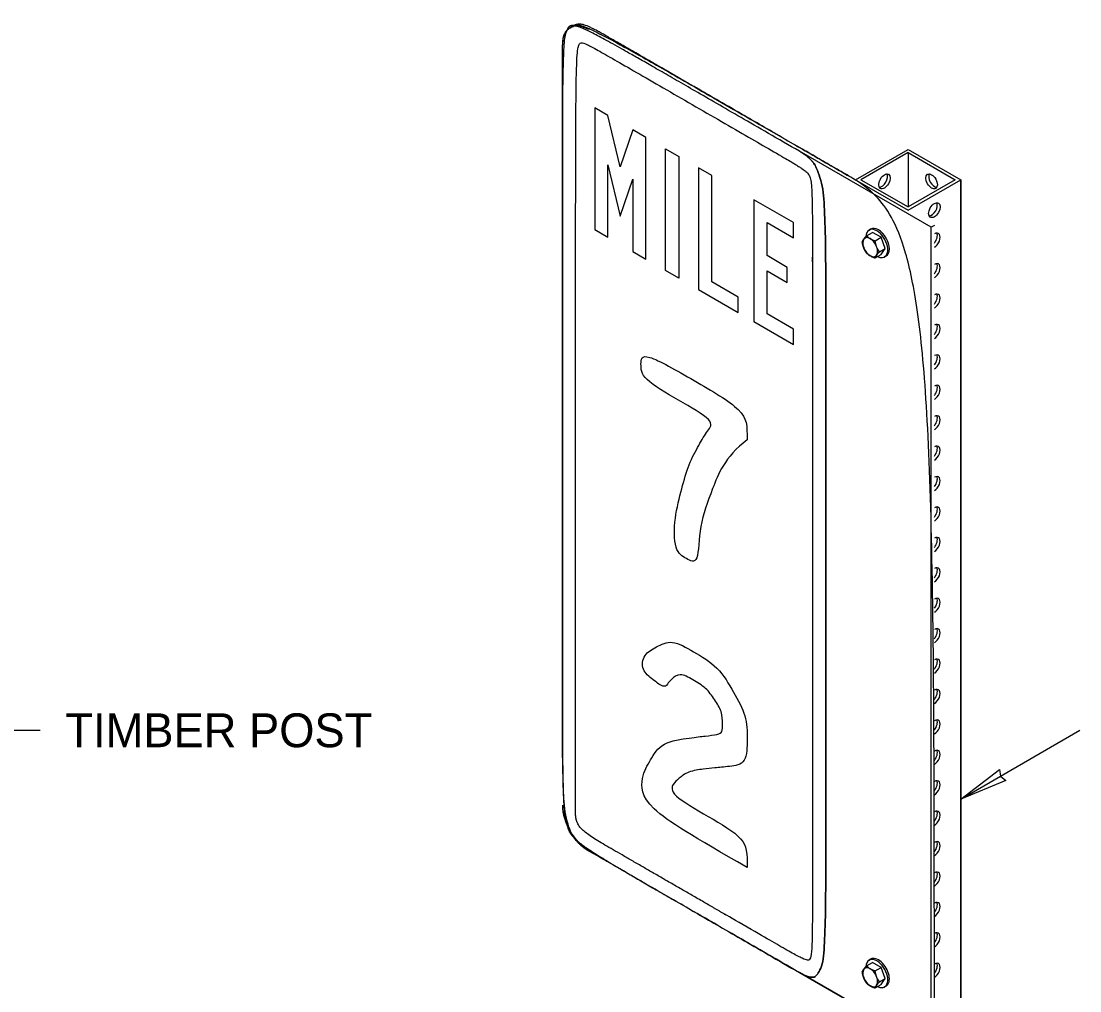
# Model space of a CAD drawing. Extents: x 99862 to 103151, y 100000 to 102076.
# Drawn here: x 102287 to 102788, y 101046 to 101505 of the extents above; entities that cross this region are included whole.
import ezdxf

# ---------------------------------------------------------------- set-up
doc = ezdxf.new("R2010")
doc.units = 0
for name, color, linetype in [('Level 15', 7, 'Continuous'), ('Level 2', 7, 'Continuous'), ('Level 20', 7, 'Continuous'), ('Level 9', 7, 'Continuous')]:
    doc.layers.add(name, color=color, linetype=linetype)

msp = doc.modelspace()

# ---------------------------------------------------------------- linework, layer by layer
at = {"layer": 'Level 15'}
for p, q in [((102280.36, 101169.56), (102296.36, 101169.56)), ((102731.44, 101137.06), (102787.74, 101169.56))]:
    msp.add_line(p, q, dxfattribs=at)
msp.add_lwpolyline([(102731.45, 101137.06), (102749.72, 101151.06), (102750.3, 101147.95), (102752.71, 101145.89)], close=True, dxfattribs=at)
at = {"layer": 'Level 2'}
for p, q in [((102548.42, 101502.35), (102546.86, 101501.45)), ((102681.67, 101429.63), (102706.56, 101444)), ((102706.56, 101442.49), (102684.28, 101429.63)), ((102706.56, 101444), (102731.45, 101429.63)), ((102706.56, 101442.49), (102706.56, 101416.77)), ((102706.56, 101442.49), (102728.83, 101429.63)), ((102715.77, 101432.21), (102715.77, 101432.21)), ((102681.67, 101429.63), (102706.56, 101415.26)), ((102684.28, 101429.63), (102706.56, 101416.77)), ((102728.83, 101429.63), (102706.56, 101416.77)), ((102706.56, 101415.26), (102731.45, 101429.63)), ((102731.45, 100984.15), (102731.45, 101429.63)), ((102719.62, 101425.54), (102719.62, 101425.54)), ((102719, 101408.07), (102717.45, 101407.17)), ((102720.93, 101404.22), (102720.93, 101404.22)), ((102720.93, 101389.85), (102720.93, 101389.85)), ((102720.93, 101375.48), (102720.93, 101375.48)), ((102720.93, 101274.89), (102720.93, 101274.89)), ((102720.93, 101260.52), (102720.93, 101260.52)), ((102720.93, 101116.82), (102720.93, 101116.82)), ((102720.93, 101059.33), (102720.93, 101059.33))]:
    msp.add_line(p, q, dxfattribs=at)
for points in [[(102546.86, 101501.45), (102548.42, 101502.35)], [(102546.86, 101501.45), (102546.86, 101501.45), (102546.86, 101501.45)], [(102655.22, 101055.1), (102717.45, 101019.18), (102717.45, 101407.17), (102655.22, 101443.1)], [(102706.56, 101025.46), (102717.45, 101019.18), (102717.45, 101407.17), (102655.22, 101443.1)], [(102681.67, 101429.63), (102706.56, 101444), (102731.45, 101429.63), (102731.45, 101029.06)], [(102688.11, 101405.89), (102688.89, 101406.34)], [(102685.6, 101401.49), (102685.67, 101401.59)], [(102685.68, 101397.37), (102685.59, 101397.62)], [(102688.75, 101393.68), (102688.58, 101393.78)], [(102692.1, 101393.38), (102692.1, 101393.38), (102692.1, 101393.38), (102692.04, 101393.34), (102691, 101392.74)], [(102696.22, 101393.64), (102696.1, 101393.74)], [(102688.11, 101061), (102688.89, 101061.45)], [(102685.6, 101056.6), (102685.67, 101056.7)], [(102681.67, 101027.26), (102681.67, 101039.83), (102655.22, 101055.1)], [(102655.22, 101055.1), (102681.67, 101039.83), (102706.56, 101025.46)], [(102685.68, 101052.49), (102685.59, 101052.73)], [(102688.75, 101048.79), (102688.58, 101048.89)], [(102692.1, 101048.49), (102692.1, 101048.49), (102692.1, 101048.49), (102692.04, 101048.45), (102691, 101047.85)], [(102696.22, 101048.75), (102696.1, 101048.85)]]:
    msp.add_lwpolyline(points, dxfattribs=at)
for points in [[(102564.74, 101459.95), (102558.52, 101463.54), (102558.52, 101406.06), (102564.74, 101402.47), (102564.74, 101436.62), (102570.59, 101412.37), (102576.44, 101429.86), (102576.44, 101395.71), (102582.67, 101392.12), (102582.67, 101449.6), (102576.44, 101453.2), (102570.59, 101435.71)], [(102592, 101444.21), (102598.22, 101440.62), (102598.22, 101383.14), (102592, 101386.73)], [(102626.22, 101374.16), (102613.78, 101381.34), (102613.78, 101431.64), (102607.56, 101435.23), (102607.56, 101377.75), (102626.22, 101366.97)], [(102649.49, 101388.26), (102639.91, 101393.79), (102639.91, 101409.37), (102652.36, 101402.18), (102652.36, 101409.37), (102633.69, 101420.14), (102633.69, 101362.66), (102652.36, 101351.88), (102652.36, 101359.07), (102639.91, 101366.26), (102639.91, 101386.61), (102649.49, 101381.08)]]:
    msp.add_lwpolyline(points, close=True, dxfattribs=at)
for centre, major_axis, start_param, end_param in [((102555.66, 101486.21), (-8.8, 15.24), 5.497787, 7.068583), ((102555.66, 101486.21), (-8.8, 15.24), 6.113032, 6.283048), ((102555.66, 101486.21), (-8.8, 15.24), 6.283048, 6.283185), ((102555.66, 101486.21), (-8.8, 15.24), 0.517036, 0.785398), ((102694.11, 101429.63), (-1.92, -3.33), 0.346291, 2.795302), ((102719, 101429.63), (1.92, -3.33), 3.487884, 5.936894), ((102717.69, 101416.01), (-1.92, -3.33), 0.346291, 2.795302), ((102692.56, 101399.99), (3.67, -6.35), 6.283184, 9.424776), ((102691.78, 101399.54), (3.67, -6.35), 3.141591, 3.891684), ((102719, 101400.89), (-1.92, -3.33), 0.785398, 3.926991), ((102717.69, 101401.64), (-1.92, -3.33), 1.286053, 2.795302), ((102691.78, 101399.54), (3.67, -6.35), 5.560453, 6.484335), ((102719, 101386.52), (-1.92, -3.33), 0.785398, 3.926991), ((102717.69, 101387.27), (-1.92, -3.33), 1.286053, 2.795302), ((102719, 101372.15), (-1.92, -3.33), 0.785398, 3.926991), ((102717.69, 101372.9), (-1.92, -3.33), 1.286053, 2.795302), ((102719, 101357.78), (-1.92, -3.33), 0.785398, 3.926991), ((102717.69, 101358.53), (-1.92, -3.33), 1.286053, 2.795302), ((102719, 101343.41), (-1.92, -3.33), 0.785398, 3.926991), ((102717.69, 101344.16), (-1.92, -3.33), 1.286053, 2.795302), ((102719, 101329.04), (-1.92, -3.33), 0.785398, 3.926991), ((102717.69, 101329.79), (-1.92, -3.33), 1.286053, 2.795302), ((102719, 101314.67), (-1.92, -3.33), 0.785398, 3.926991), ((102717.69, 101315.42), (-1.92, -3.33), 1.286053, 2.795302), ((102719, 101300.3), (-1.92, -3.33), 0.785398, 3.926991), ((102717.69, 101301.05), (-1.92, -3.33), 1.286053, 2.795302), ((102719, 101285.93), (-1.92, -3.33), 0.785398, 3.926991), ((102717.69, 101286.68), (-1.92, -3.33), 1.286053, 2.795302), ((102719, 101271.55), (-1.92, -3.33), 0.785398, 3.926991), ((102717.69, 101272.31), (-1.92, -3.33), 1.286053, 2.795302), ((102719, 101257.18), (-1.92, -3.33), 0.785398, 3.926991), ((102717.69, 101257.94), (-1.92, -3.33), 1.286053, 2.795302), ((102719, 101242.81), (-1.92, -3.33), 0.785398, 3.926991), ((102717.69, 101243.57), (-1.92, -3.33), 1.286053, 2.795302), ((102719, 101228.44), (-1.92, -3.33), 0.785398, 3.926991), ((102717.69, 101229.2), (-1.92, -3.33), 1.286053, 2.795302), ((102719, 101214.07), (-1.92, -3.33), 0.785398, 3.926991), ((102717.69, 101214.83), (-1.92, -3.33), 1.286053, 2.795302), ((102719, 101199.7), (-1.92, -3.33), 0.785398, 3.926991), ((102717.69, 101200.46), (-1.92, -3.33), 1.286053, 2.795302), ((102719, 101185.33), (-1.92, -3.33), 0.785398, 3.926991), ((102717.69, 101186.09), (-1.92, -3.33), 1.286053, 2.795302), ((102719, 101170.96), (-1.92, -3.33), 0.785398, 3.926991), ((102717.69, 101171.72), (-1.92, -3.33), 1.286053, 2.795302), ((102719, 101156.59), (-1.92, -3.33), 0.785398, 3.926991), ((102717.69, 101157.35), (-1.92, -3.33), 1.286053, 2.795302), ((102719, 101142.22), (-1.92, -3.33), 0.785398, 3.926991), ((102717.69, 101142.98), (-1.92, -3.33), 1.286053, 2.795302), ((102555.66, 101126.95), (8.8, -15.24), 3.926991, 5.497787), ((102719, 101127.85), (-1.92, -3.33), 0.785398, 3.926991), ((102717.69, 101128.61), (-1.92, -3.33), 1.286053, 2.795302), ((102719, 101113.48), (-1.92, -3.33), 0.785398, 3.926991), ((102717.69, 101114.24), (-1.92, -3.33), 1.286053, 2.795302), ((102719, 101099.11), (-1.92, -3.33), 0.785398, 3.926991), ((102717.69, 101099.87), (-1.92, -3.33), 1.286053, 2.795302), ((102719, 101084.74), (-1.92, -3.33), 0.785398, 3.926991), ((102717.69, 101085.49), (-1.92, -3.33), 1.286053, 2.795302), ((102719, 101070.37), (-1.92, -3.33), 0.785398, 3.926991), ((102717.69, 101071.12), (-1.92, -3.33), 1.286053, 2.795302), ((102692.56, 101055.1), (3.67, -6.35), 6.283185, 9.424778), ((102691.78, 101054.65), (3.67, -6.35), 3.141593, 3.891684), ((102691.78, 101054.65), (3.67, -6.35), 3.141466, 3.141593), ((102719, 101056), (-1.92, -3.33), 0.785398, 3.926991), ((102717.69, 101056.75), (-1.92, -3.33), 1.286053, 2.795302), ((102691.78, 101054.65), (3.67, -6.35), 5.560453, 6.484337)]:
    msp.add_ellipse(centre, major_axis=major_axis, ratio=0.57735, start_param=start_param, end_param=end_param, dxfattribs=at)
for centre, major_axis in [((102695.42, 101428.87), (-1.92, -3.33)), ((102717.69, 101428.87), (1.92, -3.33)), ((102719, 101415.26), (-1.92, -3.33))]:
    msp.add_ellipse(centre, major_axis=major_axis, ratio=0.57735, dxfattribs=at)
for points, degree in [([(102655.22, 101443.1), (102605.44, 101471.84), (102555.66, 101500.58), (102543.21, 101507.77), (102543.21, 101493.4), (102543.21, 101313.77), (102543.21, 101134.14), (102543.21, 101119.77), (102555.66, 101112.58), (102605.44, 101083.84), (102655.22, 101055.1)], 4), ([(102543.66, 101496.95), (102544.84, 101501.23), (102548.48, 101502.09)], 2), ([(102719, 101020.07), (102719, 101214.07), (102719, 101408.07), (102687.89, 101426.04), (102656.78, 101444), (102607, 101472.74), (102557.22, 101501.48), (102552.06, 101504.46), (102548.42, 101502.35)], 4), ([(102548.42, 101502.35), (102552.06, 101504.46), (102557.22, 101501.48), (102607, 101472.74), (102681.67, 101429.63)], 4), ([(102554.07, 101113.62), (102543.21, 101121.5), (102543.21, 101134.14), (102543.21, 101313.77), (102543.21, 101493.4), (102543.21, 101493.4), (102543.21, 101493.4)], 4), ([(102549.44, 101130.55), (102549.44, 101123.36), (102555.66, 101119.77), (102605.44, 101091.03), (102655.22, 101062.29), (102661.44, 101058.69), (102661.44, 101065.88), (102661.44, 101245.51), (102661.44, 101425.14), (102661.44, 101432.32), (102655.22, 101435.92), (102605.44, 101464.66), (102555.66, 101493.4), (102549.44, 101496.99), (102549.44, 101489.8), (102549.44, 101310.18), (102549.44, 101130.55)], 4), ([(102655.22, 101055.1), (102667.67, 101047.92), (102667.67, 101062.29), (102667.67, 101241.92), (102667.67, 101421.55), (102667.67, 101435.92), (102655.22, 101443.1)], 4), ([(102655.22, 101443.1), (102667.67, 101435.92), (102667.67, 101421.55), (102667.67, 101241.92), (102667.67, 101062.29), (102667.67, 101047.92), (102655.22, 101055.1)], 4), ([(102684.94, 101400.28), (102685.07, 101400.63), (102685.28, 101401.02), (102685.6, 101401.49)], 2), ([(102685.67, 101401.59), (102685.93, 101401.95), (102686.24, 101402.34), (102686.6, 101402.74)], 2), ([(102685.59, 101397.62), (102685.27, 101398.47), (102685.07, 101399.36), (102684.94, 101400.28)], 2), ([(102686.96, 101395.07), (102686.46, 101395.78), (102686.02, 101396.54), (102685.68, 101397.37)], 2), ([(102688.58, 101393.78), (102687.94, 101394.16), (102687.41, 101394.61), (102686.96, 101395.07)], 2), ([(102691, 101392.74), (102690.19, 101393), (102689.42, 101393.3), (102688.75, 101393.68)], 2), ([(102630.52, 101306.83), (102630.52, 101313.57), (102630.52, 101320.3), (102605.44, 101334.78), (102580.36, 101349.27), (102580.36, 101342.53), (102580.36, 101335.79), (102598.09, 101325.56), (102615.82, 101315.32), (102611.74, 101311.34), (102607.89, 101304.54), (102602.76, 101295.38), (102599.72, 101284.06), (102595.99, 101270.05), (102595.99, 101254.02), (102601.82, 101250.65), (102607.66, 101247.28), (102607.66, 101266.41), (102613.72, 101282.44), (102619.79, 101298.48), (102630.52, 101306.83)], 3), ([(102630.52, 101104.75), (102630.52, 101111.48), (102630.52, 101118.22), (102612.15, 101128.83), (102593.77, 101139.44), (102595.41, 101144.42), (102598.09, 101146.65), (102602.41, 101150.22), (102610.34, 101151.29), (102614.77, 101151.83), (102622.01, 101152.37), (102630.52, 101153.65), (102630.52, 101165.64), (102630.52, 101176.28), (102624.22, 101187.33), (102617.11, 101199.79), (102604.86, 101206.87), (102594.82, 101212.66), (102587.59, 101208.89), (102581.41, 101205.59), (102580.36, 101197.84), (102586.07, 101193.46), (102591.79, 101189.08), (102593.31, 101192.25), (102594.59, 101193.39), (102598.56, 101197.03), (102604.86, 101193.39), (102611.27, 101189.69), (102615.07, 101184.06), (102618.86, 101178.44), (102618.86, 101172.38), (102618.86, 101168.6), (102616.99, 101167.53), (102610.69, 101166.85), (102604.51, 101166.11), (102589.81, 101164.09), (102584.79, 101155.4), (102580.36, 101147.86), (102580.36, 101133.71), (102605.44, 101119.23), (102630.52, 101104.75)], 3), ([(102546.86, 101121.87), (102550.5, 101115.56), (102555.66, 101112.58)], 2), ([(102555.66, 101112.58), (102554.86, 101113.04), (102554.07, 101113.62)], 2), ([(102655.22, 101055.1), (102605.44, 101083.84), (102555.66, 101112.58), (102555.66, 101112.58), (102555.66, 101112.58)], 4), ([(102684.94, 101055.39), (102685.07, 101055.74), (102685.28, 101056.13), (102685.6, 101056.6)], 2), ([(102685.67, 101056.7), (102685.93, 101057.06), (102686.24, 101057.45), (102686.6, 101057.86)], 2), ([(102685.59, 101052.73), (102685.27, 101053.58), (102685.07, 101054.48), (102684.94, 101055.39)], 2), ([(102686.96, 101050.19), (102686.46, 101050.89), (102686.02, 101051.65), (102685.68, 101052.49)], 2), ([(102688.58, 101048.89), (102687.94, 101049.27), (102687.41, 101049.72), (102686.96, 101050.19)], 2), ([(102691, 101047.85), (102690.19, 101048.11), (102689.42, 101048.42), (102688.75, 101048.79)], 2)]:
    msp.add_open_spline(points, degree=degree, dxfattribs=at)
at = {"layer": 'Level 9'}
for p, q in [((102688.89, 101406.34), (102688.11, 101405.89)), ((102685.67, 101401.59), (102685.6, 101401.49)), ((102686.96, 101403.16), (102689.76, 101404.77)), ((102693.8, 101402.44), (102689.76, 101404.77)), ((102691, 101400.82), (102693.8, 101402.44)), ((102695.82, 101397.23), (102693.8, 101402.44)), ((102685.59, 101397.62), (102685.68, 101397.37)), ((102693.02, 101395.62), (102695.82, 101397.23)), ((102693.8, 101394.36), (102695.82, 101397.23)), ((102688.58, 101393.78), (102688.75, 101393.68)), ((102691, 101392.74), (102693.8, 101394.36)), ((102691.67, 101393.96), (102691.72, 101394.03)), ((102696.22, 101393.64), (102695.44, 101393.19)), ((102688.89, 101061.45), (102688.11, 101061)), ((102685.67, 101056.7), (102685.6, 101056.6)), ((102686.96, 101058.27), (102689.76, 101059.88)), ((102693.8, 101057.55), (102689.76, 101059.88)), ((102691, 101055.94), (102693.8, 101057.55)), ((102695.82, 101052.34), (102693.8, 101057.55)), ((102685.59, 101052.73), (102685.68, 101052.49)), ((102693.02, 101050.73), (102695.82, 101052.34)), ((102693.8, 101049.47), (102695.82, 101052.34)), ((102688.58, 101048.89), (102688.75, 101048.79)), ((102691, 101047.85), (102693.8, 101049.47)), ((102691.67, 101049.08), (102691.72, 101049.14)), ((102696.22, 101048.75), (102695.44, 101048.3))]:
    msp.add_line(p, q, dxfattribs=at)
for centre, major_axis, start_param, end_param in [((102691.78, 101399.54), (3.67, -6.35), 5.560453, 9.424776), ((102692.56, 101399.99), (3.67, -6.35), 6.283184, 9.424776), ((102688.67, 101397.77), (2.48, -4.29), 3.424282, 4.423348), ((102688.67, 101397.77), (2.48, -4.29), 2.356194, 3.382502), ((102691.78, 101399.54), (3.67, -6.35), 3.141591, 3.891684), ((102688.67, 101397.77), (2.48, -4.29), 0.274983, 2.356194), ((102688.67, 101397.77), (2.48, -4.29), 4.477831, 5.47306), ((102688.67, 101397.77), (2.48, -4.29), 5.522514, 6.531755), ((102691.78, 101054.65), (3.67, -6.35), 5.560453, 9.424778), ((102692.56, 101055.1), (3.67, -6.35), 6.283185, 9.424778), ((102688.67, 101052.88), (2.48, -4.29), 3.424282, 4.423348), ((102688.67, 101052.88), (2.48, -4.29), 2.356194, 3.382502), ((102691.78, 101054.65), (3.67, -6.35), 3.141593, 3.891684), ((102688.67, 101052.88), (2.48, -4.29), 0.274983, 2.356194), ((102688.67, 101052.88), (2.48, -4.29), 4.477831, 5.47306), ((102688.67, 101052.88), (2.48, -4.29), 5.522514, 6.531755)]:
    msp.add_ellipse(centre, major_axis=major_axis, ratio=0.57735, start_param=start_param, end_param=end_param, dxfattribs=at)
for points, degree in [([(102685.6, 101401.49), (102685.28, 101401.02), (102685.07, 101400.63), (102684.94, 101400.28)], 2), ([(102686.96, 101403.16), (102686.46, 101402.6), (102686.01, 101402.07), (102685.67, 101401.59)], 2), ([(102686.96, 101403.16), (102687.43, 101402.67), (102687.98, 101402.2), (102688.67, 101401.81)], 2), ([(102688.67, 101401.81), (102689.35, 101401.41), (102690.16, 101401.09), (102691, 101400.82)], 2), ([(102684.94, 101400.28), (102685.07, 101399.36), (102685.27, 101398.47), (102685.59, 101397.62)], 2), ([(102685.68, 101397.37), (102686.02, 101396.54), (102686.46, 101395.78), (102686.96, 101395.07)], 2), ([(102693.02, 101395.62), (102692.5, 101396.36), (102692.04, 101397.15), (102691.36, 101398.92), (102691.14, 101399.86), (102691, 101400.82)], 3), ([(102686.96, 101395.07), (102687.41, 101394.61), (102687.94, 101394.16), (102688.58, 101393.78)], 2), ([(102688.75, 101393.68), (102689.42, 101393.3), (102690.19, 101393), (102691, 101392.74)], 2), ([(102691, 101392.74), (102691.14, 101393.09), (102691.34, 101393.49), (102691.67, 101393.96)], 2), ([(102691.72, 101394.03), (102692.06, 101394.51), (102692.51, 101395.05), (102693.02, 101395.62)], 2), ([(102685.6, 101056.6), (102685.28, 101056.13), (102685.07, 101055.74), (102684.94, 101055.39)], 2), ([(102686.96, 101058.27), (102686.46, 101057.71), (102686.01, 101057.18), (102685.67, 101056.7)], 2), ([(102686.96, 101058.27), (102687.43, 101057.78), (102687.98, 101057.32), (102688.67, 101056.92)], 2), ([(102688.67, 101056.92), (102689.35, 101056.53), (102690.16, 101056.2), (102691, 101055.94)], 2), ([(102684.94, 101055.39), (102685.07, 101054.48), (102685.27, 101053.58), (102685.59, 101052.73)], 2), ([(102685.68, 101052.49), (102686.02, 101051.65), (102686.46, 101050.89), (102686.96, 101050.19)], 2), ([(102693.02, 101050.73), (102692.5, 101051.47), (102692.04, 101052.26), (102691.36, 101054.03), (102691.14, 101054.97), (102691, 101055.94)], 3), ([(102686.96, 101050.19), (102687.41, 101049.72), (102687.94, 101049.27), (102688.58, 101048.89)], 2), ([(102688.75, 101048.79), (102689.42, 101048.42), (102690.19, 101048.11), (102691, 101047.85)], 2), ([(102691, 101047.85), (102691.14, 101048.2), (102691.34, 101048.6), (102691.67, 101049.08)], 2), ([(102691.72, 101049.14), (102692.06, 101049.62), (102692.51, 101050.16), (102693.02, 101050.73)], 2)]:
    msp.add_open_spline(points, degree=degree, dxfattribs=at)

# ---------------------------------------------------------------- texts
at = {"layer": 'Level 20'}
msp.add_text('TIMBER POST', height=16, dxfattribs=at).set_placement((102308.36, 101161.56))

doc.saveas('drawing.dxf')
